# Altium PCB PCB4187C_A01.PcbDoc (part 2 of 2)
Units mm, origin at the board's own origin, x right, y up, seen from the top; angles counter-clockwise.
Board outline 30 x 45 mm, 4 copper layers (Top Layer, Signal Layer 2, Signal Layer 3, Bottom Layer), stack 1.6 mm thick; 73 components, 77 nets, 285 pads, 424 vias.
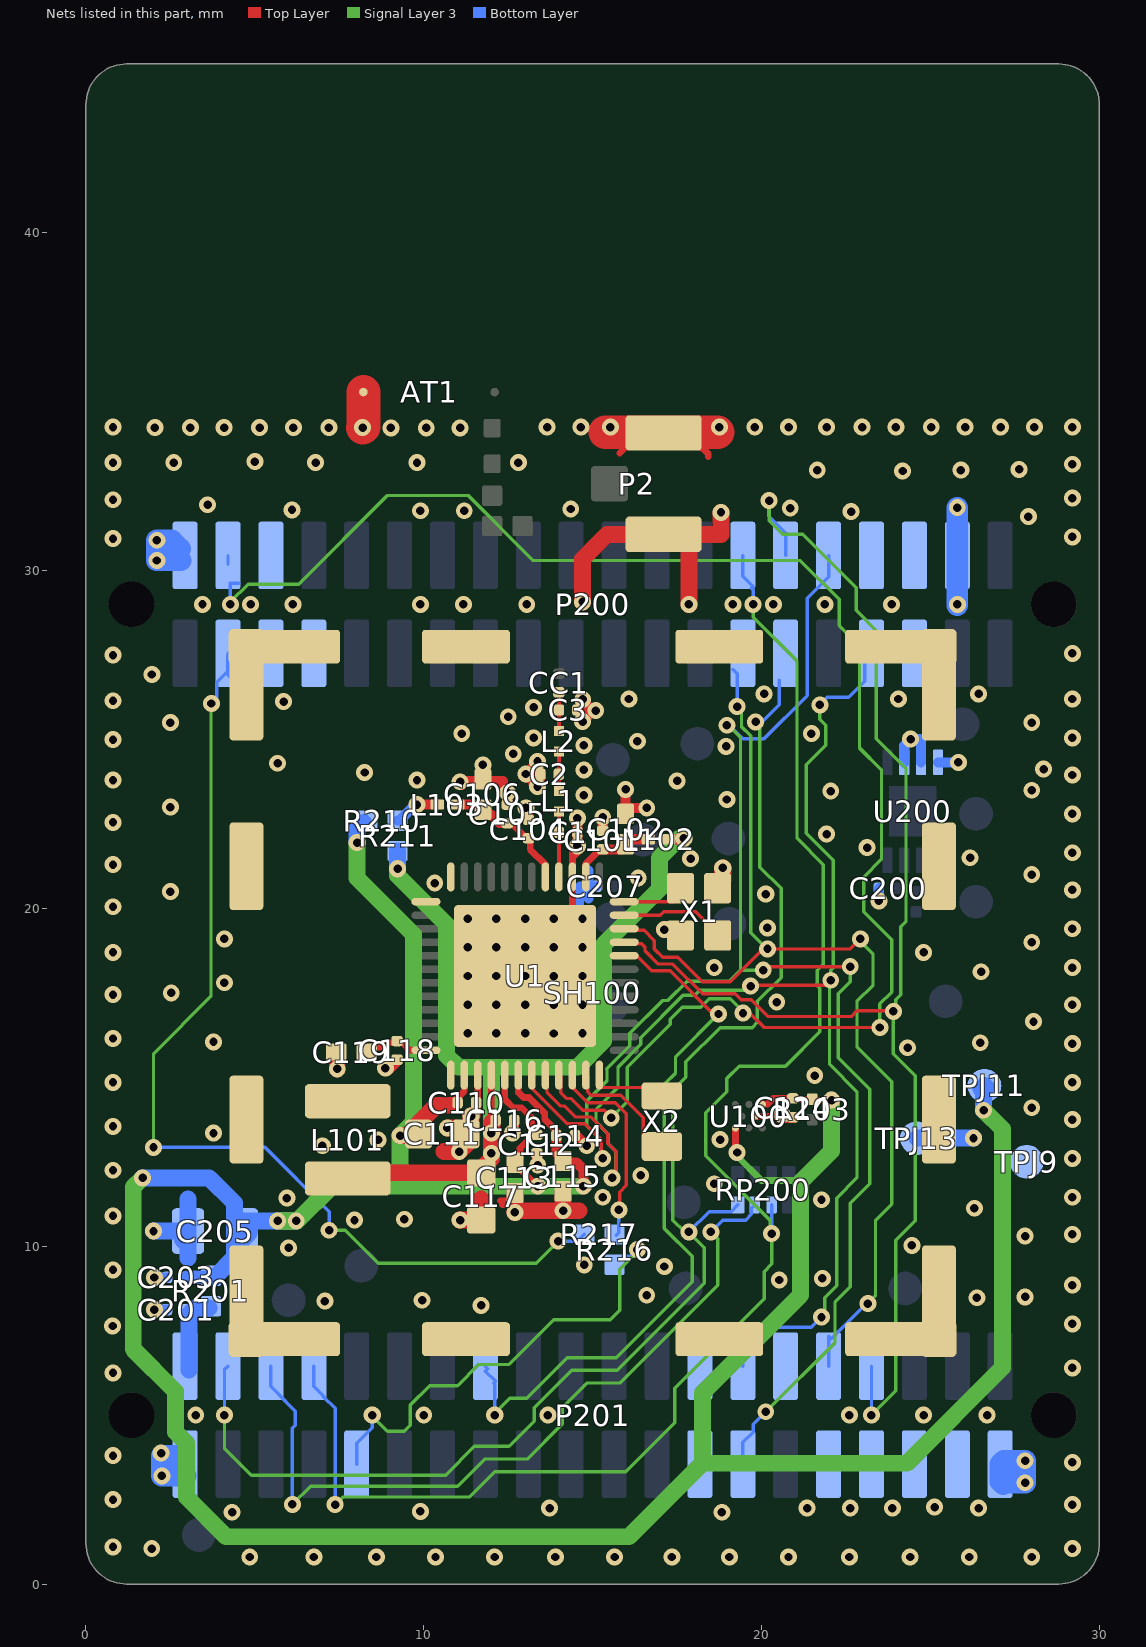
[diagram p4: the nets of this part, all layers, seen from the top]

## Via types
v1: diameter 0.5, hole 0.25, Top Layer to Bottom Layer, tented both sides, 347 vias
v2: diameter 0.508, hole 0.25, Top Layer to Bottom Layer, tented both sides, 77 vias

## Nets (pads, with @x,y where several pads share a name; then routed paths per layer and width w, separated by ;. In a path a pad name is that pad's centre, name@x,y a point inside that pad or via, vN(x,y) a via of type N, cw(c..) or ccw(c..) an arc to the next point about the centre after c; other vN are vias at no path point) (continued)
EFR32_PC07: P201.16 U1.8 | length 21.7
  Top Layer w0.1: U1.8@15.935,18.6 16.3,18.6 16.745,18.155 17.293,18.155 18.573,16.875 v2(18.725,16.875)
  Signal Layer 3 w0.1: v2@12.1,5 12.075,5.025 12.55,5.5 13.05,5.5 14.25,6.7 15.7,6.7 17.95,8.95 17.95,9.7 17.125,10.525 17.125,14.8 17.454,15.129 17.454,15.604 v2(18.725,16.875) ; v2@12.15,4.929 v2@12.198,4.977
  Bottom Layer w0.1: P201.16@11.825,6.45 11.9,6.375 11.825,6.299 12.126,5.999 12.075,5.948 12.101,5.923 v2(12.101,5)
EFR32_PC08: P200.30 P201.34 U1.9 | length 42.5
  Top Layer w0.1: U1.9@15.935,19 15.985,18.95 16.45,18.95 16.55,18.85 16.55,18.75 16.945,18.355 17.376,18.355 18.255,17.476 19.224,17.476 19.4,17.3 19.7,17.3 ; 19.701,17.301 19.701,17.299 20.2,16.8 22.65,16.8 22.825,16.975 23.8,16.975 23.901,17.076 v2(23.901,16.951)
  Signal Layer 3 w0.1: v2(20.225,32.075) 20.225,31.475 20.625,31.075 21.225,31.075 22.8,29.5 22.8,28.825 23.4,28.225 23.4,25.025 24.275,24.15 24.275,19.611 24.125,19.461 24.125,17.45 23.975,17.3 23.975,17.025 v2(23.901,16.951) 23.901,15.699 24.549,15.051 24.552,10.752 23.975,10.175 23.975,5.725 v2(23.25,5)
  Bottom Layer w0.1: v2(20.225,32.075) 20.225,31.6 20.715,31.11 P200.30@20.715,30.45 ; v2@23.25,5.05 23.255,5.055 P201.34@23.255,6.45
EFR32_PC09: P200.27 P201.32 U1.10 | length 31.7
  Top Layer w0.1: U1.10@15.935,19.4 15.985,19.35 16.525,19.35 16.825,19.05 16.825,18.8 17.07,18.555 17.52,18.555 18.25,17.825 19.075,17.825 20.051,18.801 v2(20.176,18.801) 22.626,18.801 v2(22.925,19.1)
  Signal Layer 3 w0.1: v1@19.2,25.825 19.406,25.825 19.406,25.378 19.675,25.109 19.675,19.275 20.149,18.801 v2(20.176,18.801) ; v2(22.925,19.1) v2@22.85,19.1 ; v2(23.15,8.3) 23.125,8.3 23.375,8.55 23.375,10.775 23.85,11.25 23.85,14.875 22.825,15.9 22.825,17.25 23.3,17.725 23.3,18.65 v2@22.85,19.1 ; v2@22.85,19.1 22.8,19.15 22.75,19.1 v2@22.85,19.1
  Bottom Layer w0.1: P200.27@19.15,27.075 19.276,26.949 v1(19.276,25.976) ; P201.32@21.985,6.45 21.985,7.335 22.06,7.26 v2@23.05,8.25
EFR32_PD00: U1.48 X2.1 | length 2
  Top Layer w0.1: U1.48@15.2,14.725 15.225,14.7 17.075,14.7 X2.1@17.15,14.775
EFR32_PD01: U1.47 X2.2 | length 3.7
  Top Layer w0.1: U1.47@14.8,15.065 14.85,15.015 14.85,14.575 14.95,14.475 15.825,14.475 16.5,13.8 16.5,13.275 X2.2@17.15,13.275
EFR32_PD02: R216.1 R217.1 U1.46 | length 6
  Top Layer w0.1: U1.46@14.4,15.065 14.4,14.708 14.858,14.25 15.675,14.25 16,13.925 16,11.8 15.8,11.6 v1@15.8,11.075
  Signal Layer 3 w0.1: v1@15.775,11.1 v1@15.8,11.075
  Bottom Layer w0.1: R216.1@15.7,10.325 15.775,10.4 v1(15.775,11.075)
EFR32_PD03: P200.4 U1.45 | length 49
  Top Layer w0.1: U1.45@14,15.065 14.05,15.015 14.05,14.55 14.225,14.375 14.35,14.375 14.7,14.025 15.35,14.025 15.55,13.825 v1(15.55,13.8) ; v1(19.45,16.9) 19.45,17.002 19.501,16.951 19.526,16.926 19.576,16.976 19.627,16.925 20.076,16.476 v1(23.501,16.476)
  Signal Layer 3 w0.1: v1(4.275,29) 4.275,29.075 4.8,29.6 6.3,29.6 8.925,32.225 11.318,32.225 13.243,30.3 21.15,30.3 22.3,29.15 22.3,28.375 22.9,27.775 22.9,24.75 23.55,24.1 23.55,21.45 23.025,20.925 23.025,19.9 23.85,19.075 23.85,17.525 23.497,17.172 v1@23.497,16.67 ; v1(15.55,13.8) 16.025,14.275 16.025,15.292 17.3,16.567 17.3,16.725 17.65,17.075 18.2,17.075 18.45,17.325 19.075,17.325 19.45,16.95 v1(19.45,16.9) ; v1@23.497,16.547 v1@23.497,16.628 ; v1(23.501,16.476) 23.501,16.577 23.525,16.601 v1@23.497,16.628 ; v1@23.562,16.612 23.5,16.673 v1@23.497,16.67 ; v1@23.497,16.628 23.476,16.649 v1@23.497,16.67 ; v1@23.497,16.628 v1@23.497,16.67
  Bottom Layer w0.1: P200.4@4.205,30.181 P200.4@4.205,30.45 ; v1(4.275,29) 4.275,29.625 P200.4@4.525,29.625
EFR32_PD04: P200.33 P201.28 U1.44 | length 41.7
  Top Layer w0.1: U1.44@13.6,15.065 13.65,15.015 13.65,14.55 14.05,14.15 14.175,14.15 14.5,13.825 14.953,13.825 15.45,13.328 15.45,13.05 15.701,12.799 15.701,12.151 v1(15.575,12.025) ; v1(19.676,17.701) 19.749,17.701 19.724,17.726 21.901,17.726 v1(22.05,17.875)
  Signal Layer 3 w0.1: v1(15.575,12.025) 15.7,12.15 15.7,12.8 15.45,13.05 15.45,13.328 15.1,13.678 15.1,14.05 15.75,14.7 15.75,15.3 16.425,15.975 16.425,16.175 17.675,17.425 18.025,17.425 18.175,17.575 19.525,17.575 19.701,17.751 19.751,17.701 v1(19.676,17.701) ; v1(21.725,26.025) 21.725,25.6 21.9,25.425 21.9,24.825 21.325,24.25 21.325,22.225 22.125,21.425 22.125,18.25 22.05,18.175 v1(22.05,17.875) 22.013,17.838 22.013,15.388 22.825,14.575 22.825,12.025 22.225,11.425 22.225,8.825 21.875,8.475 21.875,8.004 v1(21.775,7.904) v1@21.802,7.904
  Bottom Layer w0.1: P201.28@19.445,6.45 19.445,7.12 19.925,7.6 21.471,7.6 v1(21.775,7.904) ; v1(21.725,26.025) 21.95,26.25 22.575,26.25 23.05,26.725 23.05,27.875 P200.33@23.125,27.95
EFR32_PD05: P200.32 P201.27 U1.43 | length 47.1
  Top Layer w0.1: U1.43@13.2,15.065 13.2,14.675 14.25,13.625 14.77,13.625 15.25,13.145 v1@15.25,12.601 ; v1@20.151,18.276 v1(22.626,18.276)
  Signal Layer 3 w0.1: v1(15.3,12.601) 15.25,12.651 15.25,13.145 14.825,13.57 14.825,14.3 15.425,14.9 15.425,15.25 ; 15.421,15.254 16.1,15.933 16.1,16.3 17.075,17.275 17.221,17.275 17.796,17.85 19.05,17.85 19.375,18.175 19.375,25.075 v1@19.05,25.4 ; 19.376,18.176 v1(20.051,18.176) ; v1(20.125,5.1) 22.175,7.15 22.175,8.35 22.625,8.8 22.625,11.275 23.2,11.85 23.2,14.65 22.275,15.575 22.275,17.475 22.626,17.826 v1(22.626,18.276)
  Bottom Layer w0.1: v1(18.975,25.425) 19.05,25.425 19.45,25.025 20.072,25.025 21.35,26.303 21.35,29.18 21.985,29.815 P200.32@21.985,30.45 ; P201.27@19.445,3.55 19.445,4.195 19.75,4.5 19.75,4.725 v1(20.125,5.1) v1@20.25,5.225
GND: AT1.2 C1.2 C2.2 C3.2 C101.2 C102.2 C104.2 C105.2 C106.2 C110.2 C111.2 C112.2 C113.2 C114.2 C115.2 C116.2 C117.2 C118.2 C119.2 C124.2 C200.2 C201.2 C203.2 C205.2 C207.2 P2.2 P2.3 P200.2 P200.38 P201.1 P201.39 SH100.1 TPJ13.1 U1.0 U1.15 U1.39 U100.B2 U200.2 U200.3 U200.4 X1.2 X1.4 | length 63.2
  Top Layer w0.2: v1@2.2,3.8 v1@2.225,3.825 ; v1@9.775,23.875 v1@9.8,23.85 ; U1.0@11.35,16.4 U1.0@11.5,16.25 ; C110.2@11.6,14.3 U1.39@11.6,15.065 ; 12.275,11.35 C113.2@12.65,11.35 ; 12.325,11.225 v1@12.7,11.225 ; v1@12.375,23.575 v1@12.475,23.475 ; 14.4,21.475 U1.15@14.4,20.935 14.4,19.825 U1.0@14.5,19.725 ; v1@14.475,21.825 14.4,21.75 14.4,21.5 v1@14.675,21.775 ; 15.8,33.475 16.125,33.8 P2.3@16.2,33.8 ; P2.3@18.15,33.725 18.425,33.45 18.425,33.375 ; U100.B2@19.825,13.85 20.425,13.85 v1@20.45,13.825
  Top Layer w0.228: C106.2@11.575,23.775 C106.2@11.625,23.725 ; C106.2@11.675,23.825 11.7,23.8 C106.2@11.7,23.775
  Top Layer w0.25: v1(13.018,23.98) 13.26,23.98 C2.2@13.368,23.98 ; v1(13.368,23.605) 13.368,23.793 13.368,23.872 C2.2@13.368,23.98 ; v1(13.368,24.355) 13.368,24.107 C2.2@13.368,23.98 ; C2.2@13.475,23.98 C2.2@13.368,23.98 ; C3.2@14.525,25.87 C3.2@14.632,25.87 ; v1(14.701,25.529) 14.701,25.802 C3.2@14.632,25.87 ; v1(14.707,26.19) 14.707,25.945 C3.2@14.632,25.87 ; v1@15.053,25.8 14.82,25.8 14.75,25.87 C3.2@14.633,25.87
  Top Layer w0.3: v1@8.965,15.225 C118.2@9.19,15.45 ; v1@11.1,23.65 11.225,23.775 C106.2@11.575,23.775 ; v1(11.4,13.85) v1@11.4,13.867 ; v1@11.409,13.876 v1@11.4,13.867 ; v1@11.416,13.851 v1@11.4,13.867 ; C110.2@11.55,14.275 11.55,14.017 v1@11.4,13.867 ; v1@11.7,24.2 11.725,24.175 11.725,23.775 12.35,23.775 v1@12.35,23.575 ; C105.2@12.475,23.125 v1(12.475,23.425) v1@12.475,23.475 ; v1@12.625,13.4 12.675,13.45 C116.2@12.675,13.725 ; v1(13.018,23.98) v1@13.121,23.876 ; v1(13.018,23.98) v1@13.257,24.218 ; v1@13.05,22.975 13.1,22.925 C104.2@13.1,22.625 ; v1@13.075,23.868 v1@13.121,23.876 ; v1@13.173,23.849 13.141,23.88 v1@13.121,23.876 ; v1@13.25,23.675 v1@13.259,23.684 ; v1@13.25,23.989 13.26,23.98 13.326,23.914 13.368,23.872 13.375,23.864 13.463,23.952 13.463,23.888 13.368,23.793 v1@13.325,23.75 ; v1@13.282,23.575 v1@13.325,23.618 ; C2.2@13.325,23.913 v1@13.325,23.75 ; v1@13.333,23.608 13.333,23.665 v1@13.325,23.673 ; C112.2@13.35,12.75 13.35,12.425 v1(13.375,12.4) ; C2.2@13.475,24 13.368,24.107 v1@13.257,24.218 ; C114.2@14.475,13.275 14.495,13.295 14.505,13.295 v1(14.824,12.976) ; v1@14.525,21.875 14.55,21.9 C1.2@14.55,22.25 14.55,22.65 v1@14.575,22.675 ; v1(14.701,25.529) 14.701,25.515 14.72,25.495 v1@14.75,25.525 ; v1(14.707,26.19) 14.663,26.19 15.008,25.845 14.75,25.587 14.75,25.87 14.75,26.175 14.633,26.058 14.633,25.87 14.633,25.592 14.681,25.544 v1@14.725,25.5 ; v1@15.275,22.7 15.3,22.675 C101.2@15.3,22.3 ; C102.2@15.975,22.8 v1(15.975,23.525) v1@15.975,23.55 ; C102.2@16.05,22.9 16.125,22.975 v1(16.6,22.975) ; v1@20.525,13.825 20.55,13.8 C124.2@20.975,13.8 ; v1@13.121,23.876 13.236,23.761 13.286,23.711 v1@13.325,23.673 ; v1@13.257,24.218 13.25,24.225 13.264,24.225 v1@13.257,24.218 ; v1@13.259,23.684 v1@13.325,23.75 ; v1@13.259,23.684 v1@13.325,23.618 ; v1@13.325,23.618 v1@13.325,23.673 ; v1@13.325,23.673 v1@13.325,23.75
  Top Layer w0.5: v1(7.44,15.25) C119.2@7.44,15.7 ; 10.6,12.8 v1(11.05,12.8) 11.35,13.1 C111.2@11.35,13.2 ; v1(10.7,13.5) 10.95,13.5 11.075,13.375 C111.2@11.05,13.35 ; v1(11.075,10.775) C117.2@11.525,10.775 ; C111.2@11.401,13.176 v1@11.401,13.851 ; v1@11.4,13.851 v1@11.424,13.876 ; C117.2@11.7,10.9 11.7,11.4 ; v1(12.7,11) 12.75,11.05 14.6,11.05 ; v1@12.7,11.225 C113.2@12.7,11.575 ; v1(14.125,11.05) C115.2@14.125,11.6 ; v1(14.7,29.075) 14.7,30.35 15.425,31.075 P2.2@17.1,31.075 P2.2@17.85,31.075 ; v1(17.85,29) P2.2@17.85,31.075 ; v1(18.8,31.725) 18.8,31.075 P2.2@17.85,31.075
  Top Layer w0.508: v1(17.125,19.375) X1.2@17.275,19.375 ; X1.4@18.6,20.5 18.55,20.55 18.85,20.85 v2(18.85,21.2)
  Top Layer w1: v1(8.192,34.233) 8.214,34.255 AT1.2@8.214,35.288 ; v1@15.375,34.1 P2.3@17.1,34.1 ; P2.3@17.1,34.075 17.125,34.1 v1@18.7,34.1
  Bottom Layer w0.254: v1(0.8,9.3) v1@0.875,9.3 ; v1@1.95,8.125 v1(2.025,8.125) ; v1@1.975,9.075 v1(2.025,9.075) C203.2@2.4,9.075 ; v1@2,8.125 C201.2@2.4,8.125
  Bottom Layer w0.3: v1(2.025,8.125) 2,8.125 C201.2@2.4,8.125 ; v1(2.025,9.075) C203.2@2.4,9.075 ; v1@14.6,19.6 14.6,20.625 14.625,20.65 14.875,20.65 ; 14.875,20.3 14.875,20.65 ; 14.875,21.125 14.875,20.65 ; C207.2@15.1,20.65 14.875,20.65 ; v1@23.4,20.15 v1(23.475,20.225) v1@23.475,20.35 ; v1@23.475,20.4 C200.2@23.475,20.6 ; U200.2@24.225,24.325 24.225,24.825 v1(24.413,25.013) 24.688,25.013 24.725,24.975 U200.3@24.725,24.325 ; U200.4@25.225,24.325 v1@25.85,24.325
  Bottom Layer w0.5: v1(2,10.45) 2.9,10.45 3,10.35 2.85,10.2 C205.2@2.975,10.075 ; 3.025,9.65 C205.2@3.025,10.45 3.025,11.4 ; P200.38@25.795,30.45 P200.38@25.8,30.455
  Bottom Layer w0.508: TPJ13.1@24.6,13.2 v1(26.275,13.2)
  Bottom Layer w0.635: P201.1@2.685,3.8 2.25,3.8 v1(2.25,3.2) P201.1@2.95,3.2 ; P200.2@2.785,30.65 2.535,30.9 v1(2.1,30.9) v1(2.1,30.3) P200.2@2.8,30.3 ; v1@25.795,28.98 P200.38@25.795,30.45 v1(25.795,31.868) ; P201.39@27.065,3.55 27.165,3.65 v1(27.8,3.65) ; P201.39@27.065,3.55 27.7,3.55 v1(27.8,3.65) ; P201.39@27.065,3.55 27.065,3.035 27.15,2.95 27.2,3 v1(27.8,3) v1(27.8,3.65)
  other v1: 4.848,0.8 6.748,0.8 8.598,0.8 10.348,0.8 12.098,0.8 13.898,0.8 15.648,0.8 17.348,0.8 19.048,0.8 20.798,0.8 22.598,0.8 24.398,0.8 26.148,0.8 27.998,0.8 1.948,1.05 29.2,1.05 0.8,1.1 4.325,2.125 18.825,2.125 9.9,2.15 13.725,2.25 21.35,2.25 22.625,2.25 23.875,2.25 26.425,2.25 25.125,2.275 29.2,2.35 0.8,2.5 29.2,3.6 0.8,3.8 2.225,3.875 3.25,5 10,5 13.675,5 22.6,5 24.8,5 26.675,5 0.8,6.25 29.2,6.4 0.786,7.638 29.2,7.7 11.7,8.25 7.075,8.375 9.95,8.4 26.375,8.475 27.8,8.5 16.6,8.55 29.2,8.85 20.525,9 21.8,9.05 17.125,9.4 14.75,9.45 6,9.95 24.45,10.025 27.8,10.3 29.2,10.35 7.95,10.775 9.425,10.8 0.8,10.9 26.3,11.125 21.775,11.375 5.95,11.425 15.3,11.45 29.2,11.45 18.6,11.85 16.425,12.1 0.8,12.25 29.2,12.6 7,12.975 8.65,13.15 18.775,13.159 3.775,13.35 12.625,13.35 0.8,13.55 29.2,13.75 20.6,13.9 28,14.1 0.8,14.85 29.2,14.85 21.576,15.051 8.865,15.276 24.325,15.875 29.2,16 26.475,16.025 3.775,16.05 0.8,16.15 11.3,16.3 12.15,16.3 13,16.3 13.85,16.298 14.7,16.3 28.05,16.65 11.3,17.15 12.15,17.15 13,17.15 13.85,17.148 14.7,17.15 29.2,17.15 20.45,17.225 0.8,17.45 2.525,17.5 4.1,17.8 11.3,18 12.15,18 13,18 13.85,17.998 14.7,18 26.5,18.125 18.6,18.25 29.2,18.25 0.8,18.7 24.8,18.7 11.3,18.85 12.15,18.85 13,18.85 13.85,18.848 14.7,18.85 28,19 4.1,19.1 29.2,19.4 20.175,19.425 11.3,19.7 12.15,19.7 13,19.7 13.85,19.698 14.7,19.7 0.8,20.05 2.5,20.5 29.2,20.55 10.325,20.75 16.35,20.9 28,21 0.8,21.3 17.9,21.475 26.175,21.5 29.2,21.65 23.125,21.8 14.55,21.85 21.925,22.2 0.8,22.55 14.55,22.675 15.3,22.7 29.2,22.8 13.025,22.975 2.5,23 18.975,23.225 14.742,23.353 22.05,23.475 28,23.5 11.075,23.75 17.5,23.775 0.8,23.8 9.8,23.8 29.2,23.95 8.25,24.025 14.742,24.103 28.35,24.125 11.75,24.25 5.675,24.3 25.825,24.325 12.65,24.575 18.95,24.8 14.742,24.828 16.325,24.95 0.8,25 13.25,25.05 29.2,25.05 11.125,25.175 21.475,25.175 2.5,25.5 28,25.5 12.5,25.675 15.093,25.856 13.25,25.95 5.85,26.125 0.8,26.15 16.075,26.2 24.051,26.201 29.2,26.2 20.075,26.35 26.425,26.35 1.95,26.925 0.8,27.5 29.2,27.55 3.45,29 4.875,29 6.125,29 9.9,29 11.175,29 13.05,29 19.15,29 20.35,29 21.876,29 23.85,29 25.8,29 0.8,30.95 29.2,31 27.9,31.6 22.65,31.75 9.9,31.775 11.2,31.775 6.1,31.8 14.35,31.825 20.85,31.85 3.6,31.95 0.8,32.1 29.2,32.15 21.65,32.975 24.175,32.95 25.9,32.975 27.625,33 29.2,33.15 0.8,33.2 2.6,33.2 6.8,33.2 9.8,33.2 12.8,33.2 5,33.227 2.042,34.233 3.092,34.233 4.092,34.233 5.142,34.233 6.142,34.233 7.192,34.233 9.025,34.225 10.075,34.225 11.075,34.225 0.8,34.25 13.65,34.25 14.65,34.25 15.525,34.25 18.75,34.25 19.8,34.25 20.8,34.25 21.925,34.25 22.975,34.25 23.975,34.25 25.025,34.25 26.025,34.25 27.075,34.25 28.075,34.25 29.2,34.25
  other v2: 20.125,20.425
N17597956: L101.1 U1.37
N17597974: U1.11 X1.3 | length 3.1
  Top Layer w0.1: U1.11@15.935,19.8 17,19.8 17.1,19.9 18.05,19.9 18.65,19.3 X1.3@18.65,19.225
N17598005: U1.12 X1.1 | length 2
  Top Layer w0.1: U1.12@15.935,20.2 17.425,20.2 17.55,20.325 X1.1@17.55,20.625
N17598097: C101.1 C102.1 L102.2 U1.14 | length 2.5
  Top Layer w0.2: U1.14@14.8,20.875 U1.14@14.8,20.935
  Top Layer w0.203: U1.14@14.8,21.1 14.8,21.325 15.175,21.7 15.5,21.7
  Top Layer w0.3: C101.1@15.275,21.75 15.875,21.75 16.175,22.05 L102.2@16.5,22.05
N17598121: C104.1 C105.1 C106.1 L103.2 U1.17 | length 3.8
  Top Layer w0.2: C105.1@12.5,22.475 12.65,22.475 13.15,21.975 13.15,21.75 13.6,21.3 U1.17@13.6,20.935
  Top Layer w0.3: L103.2@11,23.075 11.6,23.075 11.9,22.775 11.994,22.775 12.244,22.525 C105.1@12.475,22.525 C105.1@12.5,22.525
N17598142: C1.1 L1.1 U1.16 | length 2
  Top Layer w0.127: U1.16@14.003,20.932 14.003,22.249 L1.1@14.003,22.91
N17598159: C2.1 L1.2 L2.1 | length 1.3
  Top Layer w0.127: L1.2@14.003,23.435 14.003,23.984 L2.1@14.003,24.701
N17598275: C3.1 CC1.1 L2.2 | length 1.2
  Top Layer w0.127: L2.2@14.003,25.226 14.003,25.873 CC1.1@14.003,26.412
N17598561: C118.1 C119.1 U1.36 | length 1.8
  Top Layer w0.2: C119.1@8.465,15.9 8.765,15.9 8.89,16.025 9.365,16.025 9.59,15.8 U1.36@10.065,15.8 U1.36@10.075,15.8
PAVDD: L103.1 R210.1 R211.2 | length 1.4
  Top Layer w0.3: v1(9.8,23.075) L103.1@10.4,23.075
  Bottom Layer w0.3: R210.1@9.225,22.6 9.275,22.6 v1@9.775,23.1
USB_VBUS: P200.35
USB_VREG: P200.36
VDCDC: C116.1 C117.1 L101.2 L102.1 R211.1 U1.40 | length 29.9
  Top Layer w0.2: C116.1@12,13.85 12,14.55 U1.40@12,14.955
  Top Layer w0.3: L102.1@17.25,22.05 17.627,22.05 17.675,22.002 v1@17.7,22.027 ; v1@17.7,22 v1@17.7,22.027 ; v1(17.7,22.075) v1@17.7,22.027
  Top Layer w0.5: L101.2@8.625,12.175 C117.1@11.55,12.175 ; C117.1@11.575,12.175 12,12.6 v1(12,12.75) ; v1@12.001,12.849 v1(12.001,13.351) 12.025,13.375 C116.1@12.025,13.685
  Signal Layer 3 w0.5: v2(9.225,21.175) 9.225,20.975 10.675,19.525 10.675,15.65 11.025,15.3 12.001,15.3 ; v1(12,12.75) v1@12,13.301 ; v1(12.001,13.351) 12.001,15.3 ; v1(17.7,22.075) 17.55,22.075 16.975,21.5 16.975,20.575 ; 12.001,15.3 14.549,15.3 15.325,16.076 15.325,18.925 ; 15.325,18.925 16.975,20.575 ; 15.325,18.925 16.975,20.575
  Bottom Layer w0.5: v2(9.225,21.175) R211.1@9.225,21.7
VMCU: C110.1 C111.1 C112.1 C113.1 C114.1 C115.1 C124.1 C203.1 C205.1 R103.2 R201.2 R210.2 TPJ11.1 U1.38 U1.41 U1.42 U100.A1 U100.E3 | length 105.9
  Top Layer w0.2: 10.625,14.025 10.775,14.025 C110.1@11,14.25 ; C110.1@10.9,14.25 10.9,14.275 10.9,14.3 11.2,14.6 U1.38@11.2,15.065 ; U1.41@12.4,15.08 U1.41@12.4,15.065 ; C113.1@12.65,12.575 12.85,12.575 12.85,12.9 13.2,13.25 13.2,13.8 12.9,14.1 12.65,14.1 12.4,14.35 12.4,14.575 ; C113.1@12.7,12.475 12.7,12.439 13.289,11.85 v1@13.375,11.85 ; U1.42@12.8,15 12.8,14.55 12.95,14.4 13.121,14.4 13.579,13.942 13.579,13.761 13.939,13.401 C114.1@13.95,13.39 ; v1@19.225,12.924 U100.E3@19.225,13.5 ; U100.A1@20.025,14.225 U100.A1@20.025,14.2 20.167,14.2 20.342,14.375 20.64,14.375 20.761,14.375 20.79,14.346 20.896,14.346 C124.1@20.925,14.375 C124.1@20.95,14.35 ; C124.1@21,14.35 R103.2@21.475,14.35 ; R103.2@21.5,14.35 21.55,14.4 21.625,14.325 v2(22.075,14.325) ; 12.4,14.575 U1.41@12.4,15.065 ; 12.4,14.575 U1.41@12.4,15.065
  Top Layer w0.3: 10.525,14.175 10.625,14.275 10.9,14.275 C110.1@11,14.275 ; C114.1@13.925,13.225 13.925,12.775 C115.1@14.125,12.575 ; C115.1@14.025,12.65 C115.1@14.05,12.625 ; C115.1@14.25,12.475 14.525,12.475 14.725,12.275 v1(14.725,11.775)
  Top Layer w0.5: v1(9.3,13.275) C111.1@9.825,13.275 ; C111.1@9.85,13.175 C111.1@9.825,13.175 ; 10.65,14.175 10.525,14.175 10.375,14.175 9.825,13.625 C111.1@9.825,13.275 ; C111.1@9.825,13.175 9.925,13.275 C111.1@9.825,13.275 ; C111.1@9.825,13.175 C111.1@9.825,13.275
  Signal Layer 3 w0.2: v1(19.276,12.776) 19.276,12.719 19.25,12.693 19.993,11.95 21.2,11.95
  Signal Layer 3 w0.5: v2(1.675,12.025) 1.4,11.75 1.4,6.95 2.65,5.7 2.65,4.5 2.975,4.175 2.975,2.575 4.15,1.4 16.075,1.4 18.25,3.575 ; v1(5.675,10.75) v1(6.225,10.75) 6.25,10.75 7.275,11.775 9.3,11.775 ; v2(8.025,21.95) 8.025,20.9 9.7,19.225 9.7,13.675 v1(9.3,13.275) 9.3,11.775 ; v1(14.725,11.775) v1(13.375,11.775) 9.3,11.775 ; v2(22.075,14.325) 22.075,12.825 21.275,12.025 21.2,11.95 21.15,11.9 21.15,8.55 18.25,5.65 18.25,3.575 ; v1(26.575,14.025) 27.13,13.47 27.13,6.405 24.3,3.575 18.25,3.575
  Bottom Layer w0.4: C203.1@3,9.075 R201.2@3.8,9.075
  Bottom Layer w0.5: v2(1.675,12.025) 3.65,12.025 4.4,11.275 C205.1@4.4,10.35 ; R201.2@3.775,9.1 3.8,9.075 4.4,9.675 C205.1@4.4,10.35 ; C205.1@4.55,10.75 v1(5.675,10.75) v1(6.225,10.75) ; C205.1@4.625,10.35 C205.1@4.4,10.35 ; v2(8.025,21.95) 8.025,22.35 R210.2@8.225,22.55
  Bottom Layer w0.508: v1(26.575,14.025) 26.575,14.575 TPJ11.1@26.5,14.65 ; TPJ11.1@26.6,14.75 TPJ11.1@26.55,14.7 ; TPJ11.1@26.65,14.7 26.6,14.65 TPJ11.1@26.55,14.7 ; TPJ11.1@26.5,14.65 TPJ11.1@26.55,14.7 ; TPJ11.1@26.5,14.65 TPJ11.1@26.55,14.7
  Bottom Layer w0.75: C205.1@4.625,10.35 4.725,10.45 C205.1@4.625,10.45
VMCU_IN: C201.1 P201.2 R201.1 | length 2.3
  Bottom Layer w0.5: P201.2@3.05,6.335 3.05,8 3.225,8.175 R201.1@3.65,8.175
VREFN: U1.24
VREFP: U1.25
VRF: TPJ9.1
WSTK_F15: P200.28 P201.8 RP200.6 | length 47.3
  Signal Layer 3 w0.1: v2(7.375,2.35) 7.6,2.575 11.35,2.575 12.1,3.325 15.975,3.325 17.425,4.775 17.425,5.8 20.075,8.45 20.075,9.25 20.3,9.475 v1(20.3,10.375) 20.4,10.375 20.4,10.425 20.25,10.575 20.25,10.775 18.35,12.675 18.35,13.95 18.975,14.575 18.975,14.966 19.343,15.334 20.709,15.334 21.725,16.35 21.725,17.634 21.65,17.709 21.65,18.175 21.825,18.35 21.825,21.3 21.05,22.075 21.05,27.325 19.75,28.625 v1(19.75,29) v1@19.775,29.025
  Bottom Layer w0.1: P201.8@6.745,6.45 6.745,5.855 P201.8@7.037,5.563 ; P201.8@7.025,5.55 7.375,5.2 v2(7.375,2.35) ; P200.28@19.445,30.45 19.445,29.83 19.75,29.525 19.7,29.475 19.75,29.425 v1(19.75,29) ; v1@20.3,10.55 RP200.6@20.3,11.225
WSTK_F16: P200.29 P201.4 RP200.8 | length 42.6
  Signal Layer 3 w0.1: v2@4.175,4.925 4.1,4.85 4.1,4.025 4.9,3.225 10.65,3.225 11.5,4.075 12.525,4.075 13.275,4.825 13.275,5.225 14.375,6.325 15.725,6.325 18.3,8.9 18.3,9.95 17.824,10.426 17.724,10.426 17.375,10.775 17.375,14.625 17.758,15.008 17.758,15.458 18.771,16.471 19.721,16.471 19.875,16.625 19.875,17.25 20.58,17.955 20.58,20.595 19.95,21.225 v1@19.95,25.525
  Bottom Layer w0.1: v2(4.1,5) 4.178,5 4.1,4.922 4.1,6.345 P201.4@4.205,6.45 ; v2(17.851,10.426) 18.45,11.025 19.1,11.025 RP200.8@19.3,11.225 ; v1(19.825,25.525) 19.825,25.6 19.9,25.675 20.038,25.538 20.525,26.025 P200.29@20.525,26.75
WSTK_F21: P200.34
WSTK_P3: P201.6 RP200.7 | length 23.6
  Signal Layer 3 w0.1: v2@6.11,2.56 v2(6.11,2.358) 6.652,2.9 11,2.9 11.8,3.7 13.063,3.7 14.1,4.737 14.1,5.225 14.825,5.95 15.8,5.95 18.7,8.85 18.7,10.225 v2(18.5,10.425)
  Bottom Layer w0.1: P201.6@5.475,6.45 5.475,5.85 5.921,5.404 5.921,5.4 6.2,5.121 6.2,4.704 6.11,4.614 v2(6.11,2.358) ; v2(18.5,10.425) 18.85,10.775 19.534,10.775 19.7,10.941 19.7,11.125 RP200.7@19.8,11.225
WSTK_P6: P201.9 R216.2 | length 13.8
  Signal Layer 3 w0.1: v2@8.6,5.15 8.6,4.85 8.925,4.525 9.421,4.525 9.6,4.704 9.6,5.3 10.175,5.875 11,5.875 11.625,6.5 12.525,6.5 13.85,7.825 15.525,7.825 15.8,8.1 15.8,9.325 v1@16.4,9.925 ; v1@16.4,9.85 v1@16.475,9.85
  Bottom Layer w0.1: P201.9@8.015,3.55 8.015,4.165 8.475,4.625 v2(8.475,5) ; R216.2@15.9,9.7 16.2,9.7 16.326,9.826 v1(16.326,9.9)
WSTK_P22: P201.25
WSTK_P23: P201.26
WSTK_P27: P201.30
WSTK_P28: P201.31
WSTK_P30: P201.33
WSTK_P32: P201.35
WSTK_P34: P201.37
WSTK_P36: P200.3 R217.2 | length 31.1
  Signal Layer 3 w0.1: v1(2,12.925) 2,15.7 3.7,17.4 3.7,26.055 v2(3.712,26.067) ; v1(7.2,10.475) 7.675,10.475 8.65,9.5 13.325,9.5 v1(13.975,10.15) v1@14.05,10.225
  Bottom Layer w0.1: v1(2,12.925) 5.3,12.925 7.2,11.025 v1@7.2,10.5 ; v2(3.712,26.067) 3.875,26.23 3.875,26.7 4.2,27.025 P200.3@4.2,27.5 ; P200.3@4.205,27.55 4.205,26.92 P200.3@4.263,26.862 ; v1@14,10.125 14.025,10.15 14.55,10.15 R217.2@14.75,10.35
WSTK_P38: P200.5
WSTK_P39: P200.6
WSTK_P40: P200.7
pads on no net: P200.M1 P200.M2 P201.40 P201.M1 P201.M2 RP200.4 RP200.5 TPJ18.1 TPJ19.1 TPJ20.1 U100.C1 U200.9

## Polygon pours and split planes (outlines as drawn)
GND on Top Layer "GND_L1" (solid, remove dead copper, pour order 58): 0,0 0,34.6 30,34.6 30,0
GND on Signal Layer 2 "GND_L2" (solid, remove dead copper, pour order 60): 0,0 0,34.6 30,34.6 30,0
GND on Bottom Layer "GND_L4" (solid, remove dead copper, pour order 64): 0,0 0,34.6 30,34.6 30,0
GND on Signal Layer 3 "GND_L3" (solid, remove dead copper, pour order 62): 0,0 0,34.6 30,34.6 30,0

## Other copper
Top Layer:
  region net N17597956: 7.762,13.8 7.763,14.8 9.05,14.8 9.75,15.5 10.912,15.5 10.912,14.65 9.9,14.65 9.05,13.8
  pour cut-out: 18.65,21.55 19.1,21.55 19.275,21.375 19.275,18.675 19.125,18.525 17.275,18.525 16.4,19.4 15.475,19.4 15.475,20.563 16.963,20.563 16.963,20.988 17.187,21.213 18.312,21.212
  pour cut-out: 15,21.325 13.3,21.325 13.3,23.184 13.509,23.393 13.509,27.3 14.492,27.3 14.492,23.158 14.575,23.075 14.8,23.075 15,22.875
  pour cut-out: 12.624,23.98 ccw(c13.018,23.98) 13.018,23.586 ccw(c13.018,23.98) 13.411,23.98 ccw(c13.018,23.98) 13.018,24.373 ccw(c13.018,23.98)
  pour cut-out: 12.974,23.605 ccw(c13.368,23.605) 13.368,23.211 ccw(c13.368,23.605) 13.762,23.605 ccw(c13.368,23.605) 13.368,23.999 ccw(c13.368,23.605)
  pour cut-out: 12.974,24.355 ccw(c13.368,24.355) 13.368,23.961 ccw(c13.368,24.355) 13.762,24.355 ccw(c13.368,24.355) 13.368,24.749 ccw(c13.368,24.355)
  pour cut-out: 15.486,25.846 ccw(c15.092,25.846) 15.092,26.239 ccw(c15.092,25.846) 14.698,25.846 ccw(c15.092,25.846) 15.092,25.452 ccw(c15.092,25.846)
  pour cut-out: 15.102,26.199 ccw(c14.709,26.199) 14.709,26.593 ccw(c14.709,26.199) 14.315,26.199 ccw(c14.709,26.199) 14.709,25.806 ccw(c14.709,26.199)
  pour cut-out: 15.093,25.526 ccw(c14.699,25.526) 14.699,25.919 ccw(c14.699,25.526) 14.305,25.526 ccw(c14.699,25.526) 14.699,25.132 ccw(c14.699,25.526)
Signal Layer 2:
  pour cut-out: 18.302,31.719 18.302,33.419 16.198,33.419 16.198,33.15 14.902,33.15 14.902,31.981 16.197,31.981 16.197,31.72
Bottom Layer:
  pour cut-out: 12.912,7.55 10.887,7.55 10.887,7.175 12.912,7.175
  pour cut-out: 23.25,26.838 21.975,26.838 21.975,26.462 23.25,26.462
  pour cut-out: 6.85,28.287 8.125,28.287 8.125,28.663 6.85,28.663
  pour cut-out: 9.25,26.838 7.975,26.838 7.975,26.462 9.25,26.462
  pour cut-out: 17.175,31.538 14.425,31.538 14.425,31.163 17.175,31.163
  pour cut-out: 20.55,2.837 14.527,2.837 14.527,2.462 20.55,2.462
  pour cut-out: 9.275,2.837 4.125,2.837 4.125,2.462 9.275,2.462
  pour cut-out: 9.425,7.538 4.475,7.538 4.475,7.163 9.425,7.163
  pour cut-out: 19.075,7.538 17.05,7.538 17.05,7.163 19.075,7.163
  pour cut-out: 21.1,11.863 19,11.863 19,11.488 21.1,11.488
  pour cut-out: 13.05,2.837 10.552,2.837 10.552,2.462 13.05,2.462
  pour cut-out: 19.625,28.663 17.025,28.663 17.025,28.287 19.625,28.287
  pour cut-out: 22.363,5.725 20.337,5.725 20.337,5.35 22.363,5.35
  pour cut-out: 13.25,31.55 11.9,31.55 11.9,31.175 13.25,31.175
  pour cut-out: 14.4,28.65 13.05,28.65 13.05,28.275 14.4,28.275
  pour cut-out: 15.55,26.825 14.2,26.825 14.2,26.45 15.55,26.45

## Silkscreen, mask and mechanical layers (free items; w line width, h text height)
Top Overlay:
  text "EFR32xG24B" at 0.85,41.4 h3.2
  text "2.4 GHz" at 1,39 h1.9
  text "20 dBm" at 1,37 h1.9
  text "QFN48" at 0.975,35 h1.9
Bottom Overlay:
  lines w0.15: 1.5,38 1.5,37 2.5,37 ; 1.5,42 1.5,43 2.5,43 ; 19.5,37 20.5,37 20.5,38 ; 19.5,43 20.5,43 20.5,42
  lines w0.152: 7.775,22.4 7.775,22.1 8.075,22.1 ; 7.775,22.8 7.775,23.1 8.075,23.1 ; 8.425,22.1 8.725,22.1 8.725,21.8 ; 8.725,21.45 8.725,21.15 9.025,21.15 ; 8.775,23 8.775,23.1 9.025,23.1 ; 9.425,21.15 9.725,21.15 9.725,21.45 ; 9.475,23.1 9.725,23.1 9.725,23 ; 9.725,22.1 9.725,22.4 ; 14.2,10.175 14.2,9.875 14.5,9.875 ; 14.2,10.575 14.2,10.875 14.5,10.875 ; 14.85,9.875 15.15,9.875 15.15,9.575 ; 15.15,9.225 15.15,8.925 15.45,8.925 ; 15.2,10.775 15.2,10.875 15.45,10.875 ; 15.85,8.925 16.15,8.925 16.15,9.225 ; 15.9,10.875 16.15,10.875 16.15,10.775 ; 16.15,9.875 16.15,10.175
  text "BOARD INFO" at 20.55,43.35 h1.6
  text "PAVDD / Config." at 12.466,23.362 h1.6
  text "VMCU" at 7.467,22.149 h1.2
  text "VDCDC" at 8.848,16.944 h1.2 r270
  text "PCB4187C Rev. A01" at 28,13.7 h1.52 r270
  text "EFR32_PD02 / Config." at 18.8,11.025 h1.6
  text "JOYSTICK" at 13.9,9.975 h1.2
  text "EXP9" at 16.375,8.5 h1.2 r270
Top Solder:
  the board outline again, w0.8
Bottom Solder:
  the board outline again, w0.8
BOARD OUTLINE 1:
  the board outline again, w0.1
Mechanical 11:
  the board outline again, w0.1
Mechanical 12:
  the board outline again, w0.1
Mechanical 15:
  lines w0.025: 69.971,-48.875 70.179,-48.875 ; 70.075,-48.979 70.075,-48.771
  lines w0.1: -0.5,0 0.5,0 ; 0,-0.5 0,0.5
Mechanical 16:
  lines w0.1: -0.5,0 0.5,0 ; 0,-0.5 0,0.5
Mechanical 26:
  lines w0.2: -122.4,-40.25 -120.775,-40.25 ; -122.4,6.425 -120.775,6.425 ; -122.4,53.1 -120.775,53.1 ; -67.75,-88.5 -67.75,-86.9 ; -67.75,99.8 -67.75,101.4 ; -14.725,-88.5 -14.725,-86.9 ; -14.725,99.8 -14.725,101.4 ; 38.3,-88.5 38.3,-86.9 ; 38.3,99.8 38.3,101.4 ; 91.325,-88.5 91.325,-86.9 ; 91.325,99.8 91.325,101.4 ; 144.35,-40.225 145.975,-40.225 ; 144.35,6.45 145.975,6.45 ; 144.35,53.125 145.975,53.125 ; 145.975,-88.5 -122.4,-88.5 -122.4,101.4 145.975,101.4 145.975,-88.475 ; -120.775,-86.9 -120.775,99.8 144.35,99.8 144.35,-86.9 -120.775,-86.9
  text "5" at -94.425,100.325 h0.5
  text "4" at -41.4,100.3 h0.5
  text "3" at 11.625,100.3 h0.5
  text "2" at 64.65,100.3 h0.5
  text "1" at 117.775,100.3 h0.5
  text "D" at 145.025,76.2 h0.5
  text "D" at -121.725,76.175 h0.5
  text "C" at 145.025,29.5 h0.5
  text "C" at -121.725,29.475 h0.5
  text "B" at 145.025,-17.175 h0.5
  text "B" at -121.725,-17.2 h0.5
  text "A" at 145.025,-63.825 h0.5
  text "A" at -121.725,-63.85 h0.5
  text "5" at -94.425,-87.975 h0.5
  text "4" at -41.4,-88 h0.5
  text "3" at 11.625,-88 h0.5
  text "2" at 64.65,-88 h0.5
  text "1" at 117.775,-88 h0.5
Mechanical 27:
  drawing of 28 lines, arcs and shapes, not listed
  text "Board Title" at 74.75,-61.95 h2.5
  text "'.CreativeName' '.2G4freq' '.2G4power' Radio Board" at 76.15,-67.5 h3.5
  text "Page Title" at 74.75,-71.675 h2.5
  text "Designed:" at 42.5,-75.425 h1.7
  text "Approved:" at 58.7,-75.425 h1.7
  text "Top Assembly" at 76.15,-75.575 h3.2
  text "TAB" at 44.025,-77.925 h2.2
  text "JEL" at 60.075,-77.925 h2.2
  text "Revision" at 132.65,-78.7 h1.7
  text "Document number" at 74.75,-78.975 h2.35
  text "Size" at 42.5,-80.175 h1.7
  text "BOM Doc. No:" at 47.425,-80.175 h1.7
  text ".BoardRevision" at 132.925,-81.75 h2.7
  text ".BoardName" at 76.15,-81.85 h3.2
  text "A4" at 43.075,-82.025 h2
  text "<>" at 48,-82.025 h2
  text "Design Created Date:" at 42.5,-84.375 h1.7
  text "Sheet Created Date:" at 74.175,-84.375 h1.7
  text "Sheet Modified Date:" at 102.6,-84.375 h1.7
  text "Sheet" at 132.65,-84.375 h1.7
  text "Monday, July 13, 2020" at 43.575,-86.325 h1.7
  text "Monday, July 13, 2020" at 75.3,-86.325 h1.7
  text "'.Print_Date'" at 103.725,-86.325 h1.7
  text "1" at 133.85,-86.325 h1.7
  text "of" at 136.975,-86.325 h1.7
  text "2" at 139.7,-86.325 h1.7
Mechanical 28:
  lines w0.2: -122.4,-40.25 -120.775,-40.25 ; -122.4,6.425 -120.775,6.425 ; -122.4,53.1 -120.775,53.1 ; -67.75,-88.5 -67.75,-86.9 ; -67.75,99.8 -67.75,101.4 ; -14.725,-88.5 -14.725,-86.9 ; -14.725,99.8 -14.725,101.4 ; 38.3,-88.5 38.3,-86.9 ; 38.3,99.8 38.3,101.4 ; 91.325,-88.5 91.325,-86.9 ; 91.325,99.8 91.325,101.4 ; 144.35,-40.225 145.975,-40.225 ; 144.35,6.45 145.975,6.45 ; 144.35,53.125 145.975,53.125 ; 145.975,-88.5 -122.4,-88.5 -122.4,101.4 145.975,101.4 145.975,-88.475 ; -120.775,-86.9 -120.775,99.8 144.35,99.8 144.35,-86.9 -120.775,-86.9
  text "5" at -94.1,100.325 h0.5
  text "4" at -41.075,100.3 h0.5
  text "3" at 11.95,100.3 h0.5
  text "2" at 64.975,100.3 h0.5
  text "1" at 117.95,100.3 h0.5
  text "D" at 145.35,76.2 h0.5
  text "D" at -121.4,76.175 h0.5
  text "C" at 145.35,29.5 h0.5
  text "C" at -121.4,29.475 h0.5
  text "B" at 145.35,-17.175 h0.5
  text "B" at -121.4,-17.2 h0.5
  text "A" at 145.35,-63.825 h0.5
  text "A" at -121.4,-63.85 h0.5
  text "5" at -94.1,-87.975 h0.5
  text "4" at -41.075,-88 h0.5
  text "3" at 11.95,-88 h0.5
  text "2" at 64.975,-88 h0.5
  text "1" at 117.95,-88 h0.5
Mechanical 29:
  drawing of 28 lines, arcs and shapes, not listed
  text "Board Title" at -51.175,-61.95 h2.5
  text "'.CreativeName' '.2G4freq' '.2G4power' Radio Board" at -52.575,-67.5 h3.5
  text "Page Title" at -51.175,-71.675 h2.5
  text "Approved:" at -35.125,-75.425 h1.7
  text "Designed:" at -18.925,-75.425 h1.7
  text "Bottom Assembly" at -52.575,-75.575 h3.2
  text "JEL" at -36.5,-77.925 h2.2
  text "TAB" at -20.45,-77.925 h2.2
  text "Revision" at -109.075,-78.7 h1.7
  text "Document number" at -51.175,-78.975 h2.35
  text "BOM Doc. No:" at -23.85,-80.175 h1.7
  text "Size" at -18.925,-80.175 h1.7
  text ".BoardRevision" at -109.339,-81.75 h2.7
  text ".BoardName" at -52.575,-81.85 h3.2
  text "<>" at -24.425,-82.025 h2
  text "A4" at -19.5,-82.025 h2
  text "Sheet" at -109.075,-84.375 h1.7
  text "Sheet Modified Date:" at -79.025,-84.375 h1.7
  text "Sheet Created Date:" at -50.6,-84.375 h1.7
  text "Design Created Date:" at -18.925,-84.375 h1.7
  text "2" at -116.125,-86.325 h1.7
  text "of" at -113.4,-86.325 h1.7
  text "2" at -110.275,-86.325 h1.7
  text "'.Print_Date'" at -80.15,-86.325 h1.7
  text "Monday, July 13, 2020" at -51.725,-86.325 h1.7
  text "Monday, July 13, 2020" at -20,-86.325 h1.7
Mechanical 30:
  lines w0.2: -126.75,-94.975 156.75,-94.975 156.75,105.5 -126.75,105.5 -126.75,-94.975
